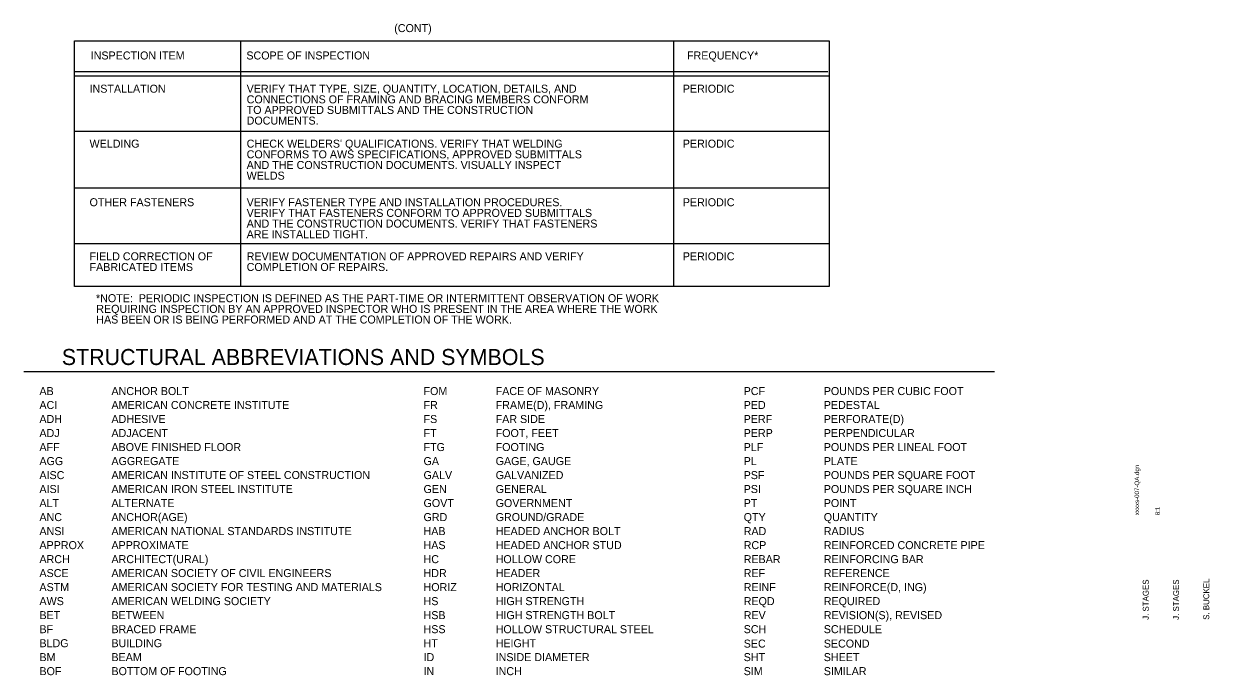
# Model space of a CAD drawing. Extents: x 2632118 to 2632142.4, y 1706724.1 to 1706788.4.
# Drawn here: x 2632126.14 to 2632138.48, y 1706730.92 to 1706737.7 of the extents above; entities that cross this region are included whole.
import ezdxf

# ---------------------------------------------------------------- set-up
doc = ezdxf.new("R2010")
doc.units = 0
doc.layers.add('S-ANNO-TEXT', color=7, linetype='Continuous')

msp = doc.modelspace()

# ---------------------------------------------------------------- linework, layer by layer
at = {"layer": 'S-ANNO-TEXT'}
for p, q in [((2632128.396, 1706737.521), (2632128.396, 1706734.964)), ((2632132.906, 1706737.521), (2632132.906, 1706734.964)), ((2632126.668, 1706737.201), (2632134.514, 1706737.201)), ((2632126.668, 1706737.157), (2632134.526, 1706737.157)), ((2632126.668, 1706737.157), (2632134.526, 1706737.157)), ((2632126.668, 1706736.581), (2632134.526, 1706736.581)), ((2632126.668, 1706735.99), (2632134.526, 1706735.99)), ((2632126.668, 1706735.41), (2632134.526, 1706735.41)), ((2632126.138, 1706734.078), (2632136.247, 1706734.078))]:
    msp.add_line(p, q, dxfattribs=at)
msp.add_lwpolyline([(2632126.668, 1706737.521), (2632134.526, 1706737.521), (2632134.526, 1706734.964), (2632126.668, 1706734.964)], close=True, dxfattribs=at)

# ---------------------------------------------------------------- texts
for s, height, p in [('(CONT)', 0.0833, (2632129.997, 1706737.612)), ('INSPECTION ITEM', 0.08333, (2632126.836, 1706737.327)), ('SCOPE OF INSPECTION', 0.08333, (2632128.457, 1706737.327)), ('FREQUENCY*', 0.0833, (2632133.046, 1706737.327)), ('INSTALLATION', 0.08333, (2632126.824, 1706736.981)), ('VERIFY THAT TYPE, SIZE, QUANTITY, LOCATION, DETAILS, AND ', 0.08333, (2632128.46, 1706736.981)), ('PERIODIC', 0.0833, (2632133.002, 1706736.981)), ('CONNECTIONS OF FRAMING AND BRACING MEMBERS CONFORM ', 0.08333, (2632128.46, 1706736.87)), ('TO APPROVED SUBMITTALS AND THE CONSTRUCTION ', 0.08333, (2632128.46, 1706736.76)), ('DOCUMENTS.', 0.0833, (2632128.46, 1706736.649)), ('WELDING ', 0.0833, (2632126.824, 1706736.409)), ("CHECK WELDERS' QUALIFICATIONS. VERIFY THAT WELDING ", 0.08333, (2632128.46, 1706736.409)), ('PERIODIC', 0.0833, (2632133.002, 1706736.409)), ('CONFORMS TO AWS SPECIFICATIONS, APPROVED SUBMITTALS ', 0.08333, (2632128.46, 1706736.298)), ('AND THE CONSTRUCTION DOCUMENTS. VISUALLY INSPECT ', 0.08333, (2632128.46, 1706736.187)), ('WELDS', 0.0833, (2632128.46, 1706736.076)), ('OTHER FASTENERS', 0.08333, (2632126.824, 1706735.799)), ('VERIFY FASTENER TYPE AND INSTALLATION PROCEDURES. ', 0.08333, (2632128.46, 1706735.799)), ('PERIODIC', 0.0833, (2632133.002, 1706735.799)), ('VERIFY THAT FASTENERS CONFORM TO APPROVED SUBMITTALS ', 0.08333, (2632128.46, 1706735.688)), ('AND THE CONSTRUCTION DOCUMENTS. VERIFY THAT FASTENERS ', 0.08333, (2632128.46, 1706735.577)), ('ARE INSTALLED TIGHT.', 0.08333, (2632128.46, 1706735.466)), ('FIELD CORRECTION OF', 0.08333, (2632126.824, 1706735.236)), ('REVIEW DOCUMENTATION OF APPROVED REPAIRS AND VERIFY ', 0.08333, (2632128.46, 1706735.236)), ('PERIODIC', 0.0833, (2632133.002, 1706735.236)), ('FABRICATED ITEMS', 0.08333, (2632126.824, 1706735.125)), ('COMPLETION OF REPAIRS.', 0.08333, (2632128.46, 1706735.125)), ('*NOTE:  PERIODIC INSPECTION IS DEFINED AS THE PART-TIME OR INTERMITTENT OBSERVATION OF WORK ', 0.08333, (2632126.891, 1706734.8)), ('REQUIRING INSPECTION BY AN APPROVED INSPECTOR WHO IS PRESENT IN THE AREA WHERE THE WORK ', 0.08333, (2632126.894, 1706734.689)), ('HAS BEEN OR IS BEING PERFORMED AND AT THE COMPLETION OF THE WORK. ', 0.08333, (2632126.894, 1706734.578)), ('STRUCTURAL ABBREVIATIONS AND SYMBOLS', 0.16667, (2632126.535, 1706734.146)), ('AB', 0.0833, (2632126.302, 1706733.833)), ('ANCHOR BOLT', 0.08333, (2632127.052, 1706733.833)), ('FOM', 0.0833, (2632130.302, 1706733.833)), ('FACE OF MASONRY', 0.08333, (2632131.053, 1706733.833)), ('PCF', 0.0833, (2632133.636, 1706733.833)), ('POUNDS PER CUBIC FOOT', 0.08333, (2632134.47, 1706733.833)), ('ACI', 0.0833, (2632126.302, 1706733.688)), ('AMERICAN CONCRETE INSTITUTE', 0.08333, (2632127.052, 1706733.688)), ('FR', 0.0833, (2632130.302, 1706733.688)), ('FRAME(D), FRAMING', 0.08333, (2632131.053, 1706733.688)), ('PED', 0.0833, (2632133.636, 1706733.688)), ('PEDESTAL', 0.0833, (2632134.47, 1706733.688)), ('ADH', 0.0833, (2632126.302, 1706733.542)), ('ADHESIVE', 0.0833, (2632127.052, 1706733.542)), ('FS', 0.0833, (2632130.302, 1706733.542)), ('FAR SIDE', 0.0833, (2632131.053, 1706733.542)), ('PERF', 0.0833, (2632133.636, 1706733.542)), ('PERFORATE(D)', 0.08333, (2632134.47, 1706733.542)), ('ADJ', 0.0833, (2632126.302, 1706733.396)), ('ADJACENT', 0.0833, (2632127.052, 1706733.396)), ('FT', 0.0833, (2632130.302, 1706733.396)), ('FOOT, FEET', 0.0833, (2632131.053, 1706733.396)), ('PERP', 0.0833, (2632133.636, 1706733.396)), ('PERPENDICULAR', 0.08333, (2632134.47, 1706733.396)), ('AFF', 0.0833, (2632126.302, 1706733.25)), ('ABOVE FINISHED FLOOR', 0.08333, (2632127.052, 1706733.25)), ('FTG', 0.0833, (2632130.302, 1706733.25)), ('FOOTING', 0.0833, (2632131.053, 1706733.25)), ('PLF', 0.0833, (2632133.636, 1706733.25)), ('POUNDS PER LINEAL FOOT', 0.08333, (2632134.47, 1706733.25)), ('AGG', 0.0833, (2632126.302, 1706733.104)), ('AGGREGATE', 0.0833, (2632127.052, 1706733.104)), ('GA', 0.0833, (2632130.302, 1706733.104)), ('GAGE, GAUGE', 0.08333, (2632131.053, 1706733.104)), ('PL', 0.0833, (2632133.636, 1706733.104)), ('PLATE', 0.0833, (2632134.47, 1706733.104)), ('AISC', 0.0833, (2632126.302, 1706732.958)), ('AMERICAN INSTITUTE OF STEEL CONSTRUCTION', 0.08333, (2632127.052, 1706732.959)), ('GALV', 0.0833, (2632130.302, 1706732.958)), ('GALVANIZED', 0.0833, (2632131.053, 1706732.958)), ('PSF', 0.0833, (2632133.636, 1706732.958)), ('POUNDS PER SQUARE FOOT', 0.08333, (2632134.47, 1706732.959)), ('AISI', 0.0833, (2632126.302, 1706732.813)), ('AMERICAN IRON STEEL INSTITUTE', 0.08333, (2632127.052, 1706732.813)), ('GEN', 0.0833, (2632130.302, 1706732.813)), ('GENERAL', 0.0833, (2632131.053, 1706732.813)), ('PSI', 0.0833, (2632133.636, 1706732.813)), ('POUNDS PER SQUARE INCH', 0.08333, (2632134.47, 1706732.813)), ('ALT', 0.0833, (2632126.302, 1706732.667)), ('ALTERNATE', 0.0833, (2632127.052, 1706732.667)), ('GOVT', 0.0833, (2632130.302, 1706732.667)), ('GOVERNMENT', 0.0833, (2632131.053, 1706732.667)), ('PT', 0.0833, (2632133.636, 1706732.667)), ('POINT', 0.0833, (2632134.47, 1706732.667)), ('ANC', 0.0833, (2632126.302, 1706732.521)), ('ANCHOR(AGE)', 0.08333, (2632127.052, 1706732.521)), ('GRD', 0.0833, (2632130.302, 1706732.521)), ('GROUND/GRADE', 0.08333, (2632131.053, 1706732.521)), ('QTY', 0.0833, (2632133.636, 1706732.521)), ('QUANTITY', 0.0833, (2632134.47, 1706732.521)), ('ANSI', 0.0833, (2632126.302, 1706732.375)), ('AMERICAN NATIONAL STANDARDS INSTITUTE', 0.08333, (2632127.052, 1706732.375)), ('HAB', 0.0833, (2632130.302, 1706732.375)), ('HEADED ANCHOR BOLT', 0.08333, (2632131.053, 1706732.375)), ('RAD', 0.0833, (2632133.636, 1706732.375)), ('RADIUS', 0.0833, (2632134.47, 1706732.375)), ('APPROX', 0.0833, (2632126.302, 1706732.229)), ('APPROXIMATE', 0.08333, (2632127.052, 1706732.229)), ('HAS', 0.0833, (2632130.302, 1706732.229)), ('HEADED ANCHOR STUD', 0.08333, (2632131.053, 1706732.229)), ('RCP', 0.0833, (2632133.636, 1706732.229)), ('REINFORCED CONCRETE PIPE', 0.08333, (2632134.47, 1706732.229)), ('ARCH', 0.0833, (2632126.302, 1706732.083)), ('ARCHITECT(URAL)', 0.08333, (2632127.052, 1706732.083)), ('HC', 0.0833, (2632130.302, 1706732.083)), ('HOLLOW CORE', 0.08333, (2632131.053, 1706732.083)), ('REBAR', 0.0833, (2632133.636, 1706732.083)), ('REINFORCING BAR', 0.08333, (2632134.47, 1706732.083)), ('ASCE', 0.0833, (2632126.302, 1706731.938)), ('AMERICAN SOCIETY OF CIVIL ENGINEERS', 0.08333, (2632127.052, 1706731.938)), ('HDR', 0.0833, (2632130.302, 1706731.938)), ('HEADER', 0.0833, (2632131.053, 1706731.938)), ('REF', 0.0833, (2632133.636, 1706731.938)), ('REFERENCE', 0.0833, (2632134.47, 1706731.938)), ('ASTM', 0.0833, (2632126.302, 1706731.792)), ('AMERICAN SOCIETY FOR TESTING AND MATERIALS', 0.08333, (2632127.052, 1706731.792)), ('HORIZ', 0.0833, (2632130.302, 1706731.792)), ('HORIZONTAL', 0.0833, (2632131.053, 1706731.792)), ('REINF', 0.0833, (2632133.636, 1706731.792)), ('REINFORCE(D, ING)', 0.08333, (2632134.47, 1706731.792)), ('AWS', 0.0833, (2632126.302, 1706731.646)), ('AMERICAN WELDING SOCIETY', 0.08333, (2632127.052, 1706731.646)), ('HS', 0.0833, (2632130.302, 1706731.646)), ('HIGH STRENGTH', 0.08333, (2632131.053, 1706731.646)), ('REQD', 0.0833, (2632133.636, 1706731.646)), ('REQUIRED', 0.0833, (2632134.47, 1706731.646)), ('BET', 0.0833, (2632126.302, 1706731.5)), ('BETWEEN', 0.0833, (2632127.052, 1706731.5)), ('HSB', 0.0833, (2632130.302, 1706731.5)), ('HIGH STRENGTH BOLT', 0.08333, (2632131.053, 1706731.5)), ('REV', 0.0833, (2632133.636, 1706731.5)), ('REVISION(S), REVISED', 0.08333, (2632134.47, 1706731.5)), ('BF', 0.0833, (2632126.302, 1706731.354)), ('BRACED FRAME', 0.08333, (2632127.052, 1706731.354)), ('HSS', 0.0833, (2632130.302, 1706731.354)), ('HOLLOW STRUCTURAL STEEL', 0.08333, (2632131.053, 1706731.354)), ('SCH', 0.0833, (2632133.636, 1706731.354)), ('SCHEDULE', 0.0833, (2632134.47, 1706731.354)), ('BLDG', 0.0833, (2632126.302, 1706731.208)), ('BUILDING', 0.0833, (2632127.052, 1706731.208)), ('HT', 0.0833, (2632130.302, 1706731.208)), ('HEIGHT', 0.0833, (2632131.053, 1706731.208)), ('SEC', 0.0833, (2632133.636, 1706731.204)), ('SECOND', 0.0833, (2632134.47, 1706731.204)), ('BM', 0.0833, (2632126.302, 1706731.063)), ('BEAM', 0.0833, (2632127.052, 1706731.063)), ('ID', 0.0833, (2632130.302, 1706731.063)), ('INSIDE DIAMETER', 0.08333, (2632131.053, 1706731.063)), ('SHT', 0.0833, (2632133.636, 1706731.063)), ('SHEET', 0.0833, (2632134.47, 1706731.063)), ('BOF', 0.0833, (2632126.302, 1706730.917)), ('BOTTOM OF FOOTING', 0.08333, (2632127.052, 1706730.917)), ('IN', 0.0833, (2632130.302, 1706730.917)), ('INCH', 0.0833, (2632131.053, 1706730.917)), ('SIM', 0.0833, (2632133.636, 1706730.917)), ('SIMILAR', 0.0833, (2632134.47, 1706730.917))]:
    msp.add_text(s, height=height, dxfattribs=at).set_placement(p)
for s, height, p in [('xxxxs-007-QA.dgn', 0.04628, (2632137.754, 1706732.582)), ('8:1', 0.0463, (2632137.969, 1706732.582)), ('J. STAGES', 0.0615, (2632137.854, 1706731.493)), ('J. STAGES', 0.0615, (2632138.169, 1706731.493)), ('S. BUCKEL', 0.0615, (2632138.484, 1706731.493))]:
    msp.add_text(s, height=height, rotation=90, dxfattribs=at).set_placement(p)

doc.saveas('drawing.dxf')
